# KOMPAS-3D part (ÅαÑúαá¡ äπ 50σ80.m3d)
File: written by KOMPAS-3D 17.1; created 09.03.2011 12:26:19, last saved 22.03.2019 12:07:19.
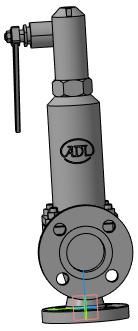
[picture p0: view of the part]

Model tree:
1. Операция без истории:1

Referenced files in C:\Users\tra\Desktop\Детали с марк. для Сферы\bsv\Desktop\Si 57\: VIC_496_50x80_3d.a3d
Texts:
  Viktor2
